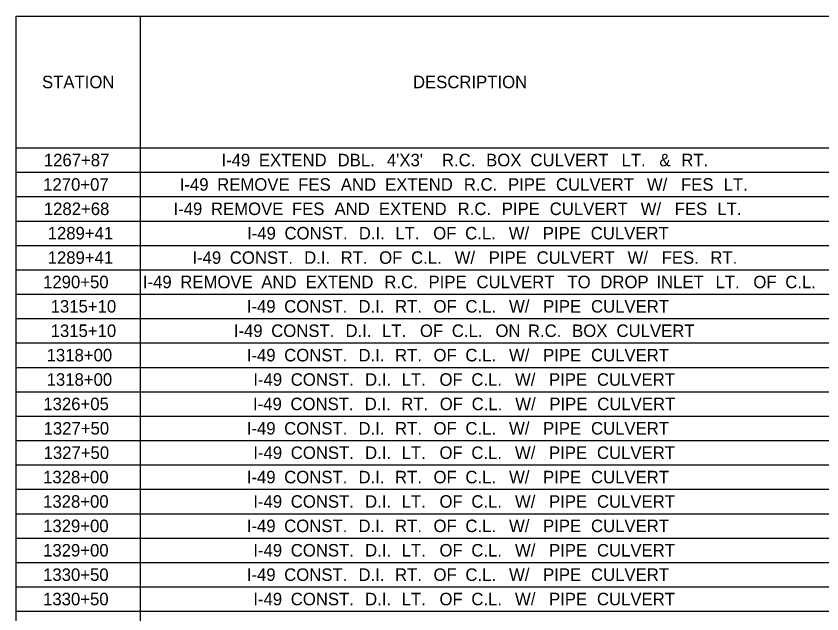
# Model space of a CAD drawing. Extents: x 1226564 to 1228153, y 151309 to 152340.
# Drawn here: x 1226563.6 to 1226838.2, y 151956.8 to 152160.5 of the extents above; entities that cross this region are included whole.
import ezdxf

# ---------------------------------------------------------------- set-up
doc = ezdxf.new("R2010")
doc.units = 0
doc.layers.add('R_Dimension', color=7, linetype='Continuous')

msp = doc.modelspace()

# ---------------------------------------------------------------- linework, layer by layer
at = {"layer": 'R_Dimension'}
for p, q in [((1226563.55, 152160.49), (1228152.75, 152160.49)), ((1226563.55, 151354.44), (1226563.55, 152160.49)), ((1226605.93, 151369.4), (1226605.93, 152160.49)), ((1226563.55, 152115.62), (1228152.75, 152115.62)), ((1226563.55, 152107.31), (1228152.75, 152107.31)), ((1226563.55, 152099), (1228152.75, 152099)), ((1226563.55, 152090.69), (1228152.75, 152090.69)), ((1226563.55, 152082.38), (1228152.75, 152082.38)), ((1226563.55, 152074.07), (1228152.75, 152074.07)), ((1226563.55, 152065.76), (1228152.75, 152065.76)), ((1226563.55, 152057.45), (1228152.75, 152057.45)), ((1226563.55, 152049.14), (1228152.75, 152049.14)), ((1226563.55, 152040.83), (1228152.75, 152040.83)), ((1226563.55, 152032.52), (1228152.75, 152032.52)), ((1226563.55, 152024.21), (1228152.75, 152024.21)), ((1226563.55, 152015.9), (1228152.75, 152015.9)), ((1226563.55, 152007.59), (1228152.75, 152007.59)), ((1226563.55, 151999.28), (1228152.75, 151999.28)), ((1226563.55, 151990.97), (1228152.75, 151990.97)), ((1226563.55, 151982.66), (1228152.75, 151982.66)), ((1226563.55, 151974.35), (1228152.75, 151974.35)), ((1226563.55, 151966.04), (1228152.75, 151966.04)), ((1226563.55, 151957.73), (1228152.75, 151957.73))]:
    msp.add_line(p, q, dxfattribs=at)

# ---------------------------------------------------------------- texts
for s, height, p in [('STATION', 4.261, (1226572.38, 152135.93)), ('DESCRIPTION', 4.2615, (1226698.83, 152135.93)), ('1267+87', 4.261, (1226573, 152109.33)), ('I-49', 4.261, (1226633.55, 152109.33)), (' EXTEND', 4.261, (1226644.72, 152109.33)), (' DBL.', 4.261, (1226671.56, 152109.33)), (" 4'X3'", 4.261, (1226688.37, 152109.33)), (' R.C.', 4.261, (1226707.13, 152109.33)), (' BOX', 4.261, (1226722.2, 152109.33)), (' CULVERT', 4.261, (1226737.33, 152109.33)), (' LT.', 4.261, (1226768.34, 152109.33)), (' &', 4.261, (1226781.25, 152109.33)), (' RT.', 4.261, (1226788.74, 152109.33)), ('1270+07', 4.261, (1226572.77, 152101.02)), ('I-49', 4.261, (1226619.34, 152101.02)), (' REMOVE', 4.261, (1226630.51, 152101.02)), (' FES', 4.261, (1226658.13, 152101.02)), (' AND', 4.261, (1226672.65, 152101.02)), (' EXTEND', 4.261, (1226687.75, 152101.02)), (' R.C.', 4.261, (1226714.6, 152101.02)), (' PIPE', 4.261, (1226729.66, 152101.02)), (' CULVERT', 4.261, (1226746, 152101.02)), (' W/', 4.261, (1226777.01, 152101.02)), (' FES', 4.261, (1226788.62, 152101.02)), (' LT.', 4.261, (1226803.15, 152101.02)), ('1282+68', 4.261, (1226573, 152092.72)), ('I-49', 4.261, (1226617.21, 152092.72)), (' REMOVE', 4.261, (1226628.38, 152092.72)), (' FES', 4.261, (1226655.99, 152092.72)), (' AND', 4.261, (1226670.52, 152092.72)), (' EXTEND', 4.261, (1226685.62, 152092.72)), (' R.C.', 4.261, (1226712.47, 152092.72)), (' PIPE', 4.261, (1226727.53, 152092.72)), (' CULVERT', 4.261, (1226743.87, 152092.72)), (' W/', 4.261, (1226774.88, 152092.72)), (' FES', 4.261, (1226786.49, 152092.72)), (' LT.', 4.261, (1226801.02, 152092.72)), ('1289+41', 4.261, (1226574.31, 152084.41)), ('I-49', 4.261, (1226642.29, 152084.41)), (' CONST.', 4.261, (1226653.46, 152084.41)), (' D.I.', 4.261, (1226678.79, 152084.41)), (' LT.', 4.261, (1226691.24, 152084.41)), (' OF', 4.261, (1226704.16, 152084.41)), (' C.L.', 4.261, (1226715.03, 152084.41)), (' W/', 4.261, (1226729.9, 152084.41)), (' PIPE', 4.261, (1226741.51, 152084.41)), (' CULVERT', 4.261, (1226757.85, 152084.41)), ('1289+41', 4.261, (1226574.31, 152076.1)), ('I-49', 4.261, (1226623.65, 152076.1)), (' CONST.', 4.261, (1226634.82, 152076.1)), (' D.I.', 4.261, (1226660.16, 152076.1)), (' RT.', 4.261, (1226672.6, 152076.1)), (' OF', 4.261, (1226685.72, 152076.1)), (' C.L.', 4.261, (1226696.6, 152076.1)), (' W/', 4.261, (1226711.46, 152076.1)), (' PIPE', 4.261, (1226723.07, 152076.1)), (' CULVERT', 4.261, (1226739.41, 152076.1)), (' W/', 4.261, (1226770.42, 152076.1)), (' FES.', 4.261, (1226782.03, 152076.1)), (' RT.', 4.261, (1226798.64, 152076.1)), ('1290+50', 4.261, (1226572.75, 152067.79)), ('I-49', 4.261, (1226606.77, 152067.79)), (' REMOVE', 4.261, (1226617.94, 152067.79)), (' AND', 4.261, (1226645.55, 152067.79)), (' EXTEND', 4.261, (1226660.65, 152067.79)), (' R.C.', 4.261, (1226687.5, 152067.79)), (' PIPE', 4.261, (1226702.56, 152067.79)), (' CULVERT', 4.261, (1226718.91, 152067.79)), (' TO', 4.261, (1226749.91, 152067.79)), (' DROP', 4.261, (1226761.12, 152067.79)), (' INLET', 4.261, (1226780.24, 152067.79)), (' LT.', 4.261, (1226800.38, 152067.79)), (' OF', 4.261, (1226813.29, 152067.79)), (' C.L.', 4.261, (1226824.17, 152067.79)), ('1315+10', 4.261, (1226575.33, 152059.48)), ('I-49', 4.261, (1226642.19, 152059.48)), (' CONST.', 4.261, (1226653.36, 152059.48)), (' D.I.', 4.261, (1226678.69, 152059.48)), (' RT.', 4.261, (1226691.14, 152059.48)), (' OF', 4.261, (1226704.26, 152059.48)), (' C.L.', 4.261, (1226715.13, 152059.48)), (' W/', 4.261, (1226730, 152059.48)), (' PIPE', 4.261, (1226741.61, 152059.48)), (' CULVERT', 4.261, (1226757.95, 152059.48)), ('1315+10', 4.261, (1226575.33, 152051.17)), ('I-49', 4.261, (1226637.76, 152051.17)), (' CONST.', 4.261, (1226648.93, 152051.17)), (' D.I.', 4.261, (1226674.26, 152051.17)), (' LT.', 4.261, (1226686.71, 152051.17)), (' OF', 4.261, (1226699.63, 152051.17)), (' C.L.', 4.261, (1226710.5, 152051.17)), (' ON', 4.261, (1226725.37, 152051.17)), (' R.C.', 4.261, (1226736.44, 152051.17)), (' BOX', 4.261, (1226751.51, 152051.17)), (' CULVERT', 4.261, (1226766.64, 152051.17)), ('1318+00', 4.261, (1226573.96, 152042.86)), ('I-49', 4.261, (1226642.19, 152042.86)), (' CONST.', 4.261, (1226653.36, 152042.86)), (' D.I.', 4.261, (1226678.69, 152042.86)), (' RT.', 4.261, (1226691.14, 152042.86)), (' OF', 4.261, (1226704.26, 152042.86)), (' C.L.', 4.261, (1226715.13, 152042.86)), (' W/', 4.261, (1226730, 152042.86)), (' PIPE', 4.261, (1226741.61, 152042.86)), (' CULVERT', 4.261, (1226757.95, 152042.86)), ('1318+00', 4.261, (1226573.96, 152034.55)), ('I-49', 4.261, (1226644.42, 152034.55)), (' CONST.', 4.261, (1226655.59, 152034.55)), (' D.I.', 4.261, (1226680.93, 152034.55)), (' LT.', 4.261, (1226693.37, 152034.55)), (' OF', 4.261, (1226706.29, 152034.55)), (' C.L.', 4.261, (1226717.16, 152034.55)), (' W/', 4.261, (1226732.03, 152034.55)), (' PIPE', 4.261, (1226743.64, 152034.55)), (' CULVERT', 4.261, (1226759.98, 152034.55)), ('1326+05', 4.261, (1226572.83, 152026.24)), ('I-49', 4.261, (1226644.32, 152026.24)), (' CONST.', 4.261, (1226655.49, 152026.24)), (' D.I.', 4.261, (1226680.82, 152026.24)), (' RT.', 4.261, (1226693.27, 152026.24)), (' OF', 4.261, (1226706.39, 152026.24)), (' C.L.', 4.261, (1226717.27, 152026.24)), (' W/', 4.261, (1226732.13, 152026.24)), (' PIPE', 4.261, (1226743.74, 152026.24)), (' CULVERT', 4.261, (1226760.08, 152026.24)), ('1327+50', 4.261, (1226572.92, 152017.93)), ('I-49', 4.261, (1226642.19, 152017.93)), (' CONST.', 4.261, (1226653.36, 152017.93)), (' D.I.', 4.261, (1226678.69, 152017.93)), (' RT.', 4.261, (1226691.14, 152017.93)), (' OF', 4.261, (1226704.26, 152017.93)), (' C.L.', 4.261, (1226715.13, 152017.93)), (' W/', 4.261, (1226730, 152017.93)), (' PIPE', 4.261, (1226741.61, 152017.93)), (' CULVERT', 4.261, (1226757.95, 152017.93)), ('1327+50', 4.261, (1226572.92, 152009.62)), ('I-49', 4.261, (1226644.42, 152009.62)), (' CONST.', 4.261, (1226655.59, 152009.62)), (' D.I.', 4.261, (1226680.93, 152009.62)), (' LT.', 4.261, (1226693.37, 152009.62)), (' OF', 4.261, (1226706.29, 152009.62)), (' C.L.', 4.261, (1226717.16, 152009.62)), (' W/', 4.261, (1226732.03, 152009.62)), (' PIPE', 4.261, (1226743.64, 152009.62)), (' CULVERT', 4.261, (1226759.98, 152009.62)), ('1328+00', 4.261, (1226572.75, 152001.31)), ('I-49', 4.261, (1226642.19, 152001.31)), (' CONST.', 4.261, (1226653.36, 152001.31)), (' D.I.', 4.261, (1226678.69, 152001.31)), (' RT.', 4.261, (1226691.14, 152001.31)), (' OF', 4.261, (1226704.26, 152001.31)), (' C.L.', 4.261, (1226715.13, 152001.31)), (' W/', 4.261, (1226730, 152001.31)), (' PIPE', 4.261, (1226741.61, 152001.31)), (' CULVERT', 4.261, (1226757.95, 152001.31)), ('1328+00', 4.261, (1226572.75, 151993)), ('I-49', 4.261, (1226644.42, 151993)), (' CONST.', 4.261, (1226655.59, 151993)), (' D.I.', 4.261, (1226680.93, 151993)), (' LT.', 4.261, (1226693.37, 151993)), (' OF', 4.261, (1226706.29, 151993)), (' C.L.', 4.261, (1226717.16, 151993)), (' W/', 4.261, (1226732.03, 151993)), (' PIPE', 4.261, (1226743.64, 151993)), (' CULVERT', 4.261, (1226759.98, 151993)), ('1329+00', 4.261, (1226572.75, 151984.69)), ('I-49', 4.261, (1226642.19, 151984.69)), (' CONST.', 4.261, (1226653.36, 151984.69)), (' D.I.', 4.261, (1226678.69, 151984.69)), (' RT.', 4.261, (1226691.14, 151984.69)), (' OF', 4.261, (1226704.26, 151984.69)), (' C.L.', 4.261, (1226715.13, 151984.69)), (' W/', 4.261, (1226730, 151984.69)), (' PIPE', 4.261, (1226741.61, 151984.69)), (' CULVERT', 4.261, (1226757.95, 151984.69)), ('1329+00', 4.261, (1226572.75, 151976.38)), ('I-49', 4.261, (1226644.42, 151976.38)), (' CONST.', 4.261, (1226655.59, 151976.38)), (' D.I.', 4.261, (1226680.93, 151976.38)), (' LT.', 4.261, (1226693.37, 151976.38)), (' OF', 4.261, (1226706.29, 151976.38)), (' C.L.', 4.261, (1226717.16, 151976.38)), (' W/', 4.261, (1226732.03, 151976.38)), (' PIPE', 4.261, (1226743.64, 151976.38)), (' CULVERT', 4.261, (1226759.98, 151976.38)), ('1330+50', 4.261, (1226572.75, 151968.07)), ('I-49', 4.261, (1226642.19, 151968.07)), (' CONST.', 4.261, (1226653.36, 151968.07)), (' D.I.', 4.261, (1226678.69, 151968.07)), (' RT.', 4.261, (1226691.14, 151968.07)), (' OF', 4.261, (1226704.26, 151968.07)), (' C.L.', 4.261, (1226715.13, 151968.07)), (' W/', 4.261, (1226730, 151968.07)), (' PIPE', 4.261, (1226741.61, 151968.07)), (' CULVERT', 4.261, (1226757.95, 151968.07)), ('1330+50', 4.261, (1226572.75, 151959.76)), ('I-49', 4.261, (1226644.42, 151959.76)), (' CONST.', 4.261, (1226655.59, 151959.76)), (' D.I.', 4.261, (1226680.93, 151959.76)), (' LT.', 4.261, (1226693.37, 151959.76)), (' OF', 4.261, (1226706.29, 151959.76)), (' C.L.', 4.261, (1226717.16, 151959.76)), (' W/', 4.261, (1226732.03, 151959.76)), (' PIPE', 4.261, (1226743.64, 151959.76)), (' CULVERT', 4.261, (1226759.98, 151959.76))]:
    msp.add_text(s, height=height, dxfattribs=at).set_placement(p)

doc.saveas('drawing.dxf')
